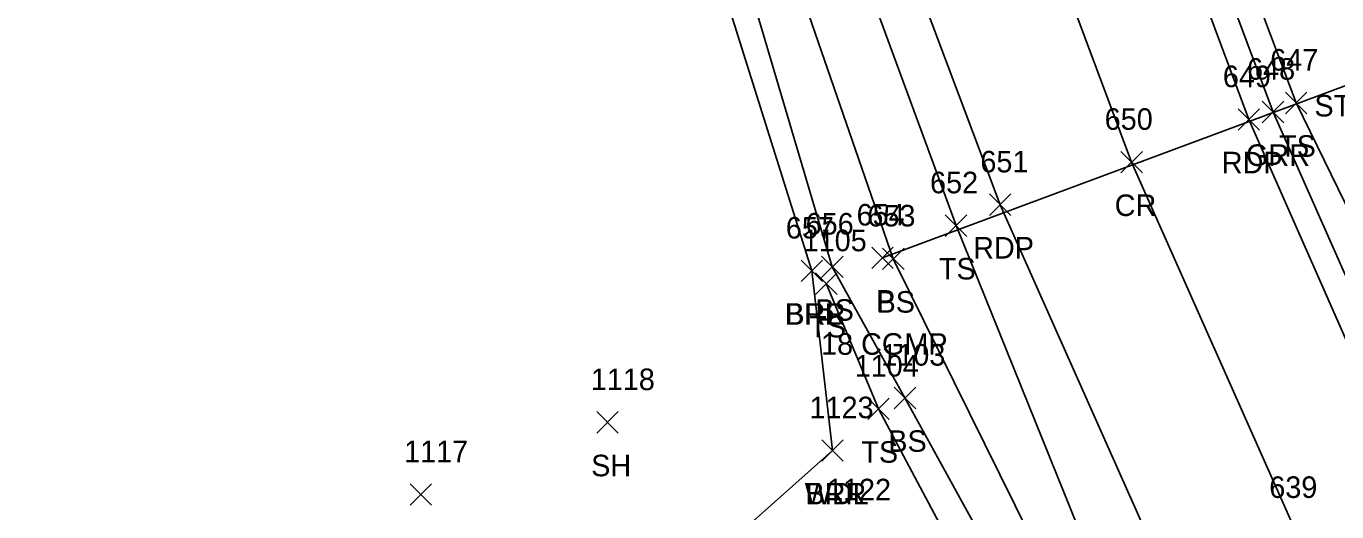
# Model space of a CAD drawing. Extents: x 1879695 to 1880991, y 836466 to 845172.
# Drawn here: x 1879765.9 to 1879887.6, y 844455.9 to 844501 of the extents above; entities that cross this region are included whole.
import ezdxf

# ---------------------------------------------------------------- set-up
doc = ezdxf.new("R2010")
doc.units = 0
for name, color, linetype in [('D_A', 7, 'Continuous'), ('D_C', 7, 'Continuous'), ('D_I', 7, 'Continuous'), ('D_TIC', 7, 'Continuous'), ('DCP', 7, 'Continuous'), ('L_A', 7, 'Continuous'), ('L_I', 7, 'Continuous'), ('L_TIC', 7, 'Continuous'), ('LABL', 7, 'Continuous'), ('LAWA', 7, 'Continuous'), ('LELB', 7, 'Continuous'), ('P_A', 7, 'Continuous'), ('P_I', 7, 'Continuous'), ('P_TIC', 7, 'Continuous'), ('PET', 7, 'Continuous'), ('PRC', 7, 'Continuous'), ('R_A', 7, 'Continuous'), ('R_I', 7, 'Continuous'), ('R_TIC', 7, 'Continuous'), ('RGR', 7, 'Continuous')]:
    doc.layers.add(name, color=color, linetype=linetype)

msp = doc.modelspace()

# ---------------------------------------------------------------- linework, layer by layer
at = {"layer": 'D_TIC'}
for points in [[(1879844.41, 844478.5), (1879846.41, 844480.5)], [(1879846.41, 844478.5), (1879844.41, 844480.5)]]:
    msp.add_lwpolyline(points, dxfattribs=at)
at = {"layer": 'DCP'}
msp.add_lwpolyline([(1879845.41, 844479.5), (1879894.42, 844497.73)], dxfattribs=at)
at = {"layer": 'L_TIC'}
for points in [[(1879882.81, 844492.88), (1879884.81, 844494.88)], [(1879884.81, 844492.88), (1879882.81, 844494.88)], [(1879851.23, 844481.49), (1879853.23, 844483.49)], [(1879853.23, 844481.49), (1879851.23, 844483.49)], [(1879845.41, 844478.41), (1879847.41, 844480.41)], [(1879847.41, 844478.41), (1879845.41, 844480.41)], [(1879837.84, 844477.29), (1879839.84, 844479.29)], [(1879839.84, 844477.29), (1879837.84, 844479.29)], [(1879837.84, 844477.29), (1879839.84, 844479.29)], [(1879839.84, 844477.29), (1879837.84, 844479.29)], [(1879839.74, 844477.66), (1879841.74, 844479.66)], [(1879841.74, 844477.66), (1879839.74, 844479.66)], [(1879839.74, 844477.66), (1879841.74, 844479.66)], [(1879841.74, 844477.66), (1879839.74, 844479.66)], [(1879839.19, 844476.11), (1879841.19, 844478.11)], [(1879841.19, 844476.11), (1879839.19, 844478.11)], [(1879846.49, 844465.49), (1879848.49, 844467.49)], [(1879848.49, 844465.49), (1879846.49, 844467.49)], [(1879846.49, 844465.49), (1879848.49, 844467.49)], [(1879848.49, 844465.49), (1879846.49, 844467.49)], [(1879844.03, 844464.48), (1879846.03, 844466.48)], [(1879846.03, 844464.48), (1879844.03, 844466.48)], [(1879818.88, 844463.22), (1879820.88, 844465.22)], [(1879820.88, 844463.22), (1879818.88, 844465.22)], [(1879839.76, 844460.61), (1879841.76, 844462.61)], [(1879841.76, 844460.61), (1879839.76, 844462.61)], [(1879839.76, 844460.61), (1879841.76, 844462.61)], [(1879841.76, 844460.61), (1879839.76, 844462.61)], [(1879801.55, 844456.53), (1879803.55, 844458.53)], [(1879803.55, 844456.53), (1879801.55, 844458.53)]]:
    msp.add_lwpolyline(points, dxfattribs=at)
at = {"layer": 'LABL'}
for points in [[(1879838.84, 844478.29), (1879827.4, 844514.75), (1879815.43, 844560.66), (1879806.77, 844599.89), (1879795.18, 844646.79), (1879789.74, 844677.99)], [(1879838.84, 844478.29), (1879840.76, 844461.61)]]:
    msp.add_lwpolyline(points, dxfattribs=at)
at = {"layer": 'LAWA'}
msp.add_lwpolyline([(1879751.37, 844393.55), (1879769.65, 844396.27), (1879790.46, 844419.82), (1879805.93, 844425.57), (1879817.22, 844439.81), (1879827.46, 844449.75), (1879840.76, 844461.61)], dxfattribs=at)
at = {"layer": 'LELB'}
for points in [[(1879840.74, 844478.66), (1879829.75, 844515.78), (1879817.77, 844560.78), (1879808.57, 844599.66), (1879797.58, 844646.67), (1879792.29, 844679.84), (1879789.08, 844683.63), (1879788.58, 844684.77), (1879788.56, 844689.11), (1879790.67, 844689.03), (1879791.23, 844733), (1879790.4, 844776.52), (1879790.9, 844833.29), (1879792.57, 844880.83), (1879794.66, 844928.51), (1879796.6, 844970.46), (1879795.45, 845013.86), (1879797.69, 845051.68), (1879797.82, 845087.62), (1879798.32, 845126.29), (1879799.71, 845166.01)], [(1879892.86, 844475.33), (1879883.81, 844493.88), (1879869.59, 844531.53), (1879857.27, 844570.41), (1879848, 844610.42), (1879840.98, 844651.69), (1879836.74, 844689.33), (1879832.5, 844735.02), (1879831.42, 844779.25), (1879830.94, 844828.14), (1879831.12, 844883.89), (1879831.78, 844926.93), (1879832.17, 844972.31), (1879832.24, 845014.04), (1879832.59, 845051.89), (1879833.37, 845086.82), (1879834.06, 845125.48), (1879835.58, 845163.13)], [(1880237.65, 844030.17), (1880225.55, 844045.25), (1880203.19, 844067.94), (1880175.04, 844095.38), (1880141.55, 844124.24), (1880111.59, 844152.12), (1880079.67, 844179.09), (1880044.89, 844208.16), (1880013.5, 844237.54), (1880003.34, 844247.82), (1879979.16, 844270.62), (1879948.51, 844300.87), (1879928.97, 844335.67), (1879901.59, 844373.87), (1879881.39, 844405.75), (1879863.37, 844445.07), (1879846.41, 844479.41), (1879833.35, 844517.23), (1879821, 844560.9), (1879811.24, 844600.26), (1879800.64, 844646.71), (1879794.2, 844680.16), (1879792.03, 844683.6), (1879789.08, 844683.63)], [(1880243.53, 844023.94), (1880226.64, 844046.28), (1880204.68, 844069.12), (1880177.19, 844097.39), (1880144.15, 844127.37), (1880114.34, 844154.46), (1880082.65, 844181.38), (1880047.53, 844211.78), (1880015.32, 844240.12), (1879982.29, 844271.84), (1879951.96, 844303.04), (1879930.28, 844336.91), (1879904.08, 844374.32), (1879883.92, 844406.9), (1879866.98, 844446.02), (1879852.23, 844482.49), (1879838.68, 844519.35), (1879826.86, 844562.48), (1879815.22, 844600.52)], [(1879840.74, 844478.66), (1879847.49, 844466.49)], [(1879859.38, 844434.9), (1879856.66, 844443.62), (1879845.03, 844465.48), (1879840.19, 844477.11)], [(1879868.08, 844418.79), (1879863.7, 844430.91), (1879859.4, 844444.83), (1879847.49, 844466.49)]]:
    msp.add_lwpolyline(points, dxfattribs=at)
at = {"layer": 'P_TIC'}
for points in [[(1879878.41, 844491.34), (1879880.41, 844493.34)], [(1879880.41, 844491.34), (1879878.41, 844493.34)], [(1879867.53, 844487.38), (1879869.53, 844489.38)], [(1879869.53, 844487.38), (1879867.53, 844489.38)], [(1879855.33, 844483.43), (1879857.33, 844485.43)], [(1879857.33, 844483.43), (1879855.33, 844485.43)]]:
    msp.add_lwpolyline(points, dxfattribs=at)
at = {"layer": 'PET'}
for points in [[(1880269.75, 844039.67), (1880250.27, 844065.9), (1880225.97, 844090.31), (1880195.98, 844117.55), (1880162.1, 844148.13), (1880132.62, 844174.7), (1880101.36, 844203.03), (1880066.94, 844232.59), (1880034.5, 844263.16), (1880004.09, 844293.64), (1879978.17, 844323.39), (1879954.46, 844354.82), (1879930.76, 844391.37), (1879912.37, 844423.12), (1879894.17, 844458.9), (1879879.41, 844492.34), (1879865.46, 844529.81), (1879852.88, 844569.32), (1879843.17, 844608.03)], [(1880246.17, 844024.86), (1880229.35, 844048.54), (1880207.67, 844072.23), (1880179.65, 844099.99), (1880146.48, 844130.19), (1880116.3, 844156.76), (1880085.61, 844184.86), (1880050.42, 844215.32), (1880017.65, 844245.83), (1879986.99, 844277.13), (1879959.04, 844308.59), (1879934.2, 844340.79), (1879910.26, 844378.73), (1879891.14, 844411.43), (1879872.36, 844448.44), (1879856.33, 844484.43), (1879842.37, 844521.56), (1879829.6, 844563.28), (1879820.43, 844602.23)]]:
    msp.add_lwpolyline(points, dxfattribs=at)
at = {"layer": 'PRC'}
msp.add_lwpolyline([(1880256.85, 844032.04), (1880238.91, 844056.2), (1880216.7, 844080.65), (1880187.27, 844108.93), (1880154.23, 844138.82), (1880124.19, 844165.48), (1880092.74, 844193.41), (1880058.56, 844223.39), (1880025.99, 844253.92), (1879995.14, 844285.41), (1879968.79, 844316.24), (1879945.09, 844347.91), (1879920.67, 844385.19), (1879902.45, 844417.14), (1879883.72, 844454.21), (1879868.53, 844488.38), (1879854.47, 844526.01), (1879841.81, 844566.38), (1879832.13, 844605)], dxfattribs=at)
at = {"layer": 'R_TIC'}
for points in [[(1879880.66, 844492.03), (1879882.66, 844494.03)], [(1879882.66, 844492.03), (1879880.66, 844494.03)]]:
    msp.add_lwpolyline(points, dxfattribs=at)
at = {"layer": 'RGR'}
msp.add_lwpolyline([(1880270.9, 844040.93), (1880251.09, 844066.69), (1880226.93, 844091.38), (1880197.34, 844118.12), (1880162.87, 844149.15), (1880133.45, 844175.62), (1880101.92, 844203.72), (1880067.67, 844234.21), (1880035.3, 844264.37), (1880005.3, 844294.8), (1879979.45, 844324.37), (1879956.29, 844356.24), (1879932.57, 844392.56), (1879914.54, 844423.96), (1879896.38, 844459.86), (1879881.66, 844493.03), (1879867.6, 844530.61), (1879855.21, 844570.01), (1879845.36, 844608.98)], dxfattribs=at)

# ---------------------------------------------------------------- texts
at = {"layer": 'D_A'}
msp.add_text('P', height=2, dxfattribs=at).set_placement((1879844.79, 844474.5))
at = {"layer": 'D_C'}
msp.add_text('18 CGMP', height=2, dxfattribs=at).set_placement((1879839.7, 844470.5))
at = {"layer": 'D_I'}
msp.add_text('654', height=2, dxfattribs=at).set_placement((1879843, 844482.5))
at = {"layer": 'L_A'}
for s, p in [('STONE', (1879885.5, 844492.62)), ('TS', (1879882.22, 844488.88)), ('TS', (1879850.64, 844477.49)), ('BS', (1879839.18, 844473.66)), ('BS', (1879839.18, 844473.66)), ('BS', (1879844.85, 844474.41)), ('BRR', (1879836.33, 844473.29)), ('BRL', (1879836.39, 844473.29)), ('TS', (1879838.6, 844472.11)), ('BS', (1879845.94, 844461.49)), ('BS', (1879845.94, 844461.49)), ('TS', (1879843.44, 844460.48)), ('SH', (1879818.36, 844459.22)), ('WDL', (1879838.18, 844456.61)), ('BRR', (1879838.25, 844456.61))]:
    msp.add_text(s, height=2, dxfattribs=at).set_placement(p)
at = {"layer": 'L_I'}
for s, p in [('647', (1879881.4, 844496.88)), ('652', (1879849.82, 844485.49)), ('653', (1879844, 844482.41)), ('657', (1879836.43, 844481.29)), ('657', (1879836.43, 844481.29)), ('656', (1879838.27, 844481.66)), ('656', (1879838.27, 844481.66)), ('1105', (1879837.99, 844480.11)), ('1104', (1879842.82, 844468.48)), ('1103', (1879845.29, 844469.49)), ('1103', (1879845.29, 844469.49)), ('1118', (1879818.32, 844467.22)), ('1123', (1879838.63, 844464.61)), ('1123', (1879838.63, 844464.61)), ('1117', (1879800.99, 844460.53)), ('1122', (1879840.25, 844456.99)), ('1122', (1879840.25, 844456.99))]:
    msp.add_text(s, height=2, dxfattribs=at).set_placement(p)
at = {"layer": 'P_A'}
for s, p in [('RDP', (1879876.9, 844487.34)), ('CR', (1879866.96, 844483.38)), ('RDP', (1879853.82, 844479.43))]:
    msp.add_text(s, height=2, dxfattribs=at).set_placement(p)
at = {"layer": 'P_I'}
for s, p in [('649', (1879877, 844495.34)), ('650', (1879866.03, 844491.38)), ('651', (1879854.49, 844487.43)), ('639', (1879881.31, 844457.21))]:
    msp.add_text(s, height=2, dxfattribs=at).set_placement(p)
at = {"layer": 'R_A'}
msp.add_text('GRR', height=2, dxfattribs=at).set_placement((1879879.15, 844488.03))
at = {"layer": 'R_I'}
msp.add_text('648', height=2, dxfattribs=at).set_placement((1879879.25, 844496.03))

doc.saveas('drawing.dxf')
